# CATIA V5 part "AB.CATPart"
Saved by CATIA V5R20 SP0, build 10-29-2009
Part number: ab
Bounding box of the stored display mesh (mm): x -10 to 5, y -76.416 to 43.584, z 30.028 to 49.972
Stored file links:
  C:\Users\Willy\Documents\ThinkMotion\646\AB.CATPart
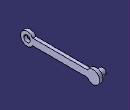
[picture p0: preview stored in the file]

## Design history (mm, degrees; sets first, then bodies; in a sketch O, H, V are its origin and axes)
Parameters
  `Longueur bièle` = 100 mm
Body1 (main body)
  Sketch1 on yz-plane, origin (0, 0, 0), H (0, 1, 0), V (0, 0, 1)
    line L1 (-57.7553, 45) -> (24.9242, 45)
    line L2 (-57.7553, 35) -> (24.9242, 35)
    axis line L3 (-76.4155, 40) -> (33.5845, 40)
    point P5 (-76.4155, 40)
    arc A1 centre (-66.4155, 40) radius 10 from (-57.7553, 45) to (-57.7553, 35) ccw
    point P7 (-66.4155, 40)
    arc A2 centre (33.5845, 40) radius 10 from (24.9242, 35) to (24.9242, 45) ccw
    point P8 (33.5845, 40)
    circle A3 centre (33.5845, 40) radius 5
    circle A4 centre (-66.4155, 40) radius 5
    distance L2 L1 = 10
    radius A1 = 10
    radius A2 = 10
    distance P8 P7 = 100 {= `Longueur bièle`}
    radius A3 = 5
    radius A4 = 5
    horizontal: L1 H, L2 H, L3 H
    coincidence: A1 P5, P7 L3, P8 L3
    symmetry: L2 L1 L3
  Pad1: profile Sketch1, direction (1, 0, 0), length 5
  Sketch2 on end face of Pad1, origin (5, 0, 0), H (0, 1, 0), V (0, 0, 1)
    circle A1 centre (33.5845, 40) radius 5
    reference projected circle E1 centre (33.5845, 40) radius 5 from edge [end face of Pad1 | face of Pad1 from Sketch1.A3]
    coincidence: A1 E1
  Pad2: profile Sketch2, direction (-1, 0, 0), length 15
